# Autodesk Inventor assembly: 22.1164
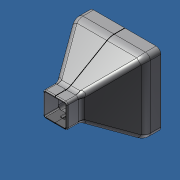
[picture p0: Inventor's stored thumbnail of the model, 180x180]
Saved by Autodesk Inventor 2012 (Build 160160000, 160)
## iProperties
Created: 2018-02
Part Number: 22.1164
Document SubType Name: Assembly
Designer: Admin
Description: COVER FOR FOOT 45
Author: Admin
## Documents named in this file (2)
- Y:\INVENTOR LIBRARIES\PARTS LIBRARY\FEET WHEELS FLOOR FASTENING SUPPORTS\22.1164 COVER FOR FOOT 45.iam
- Y:\INVENTOR LIBRARIES\PARTS LIBRARY\FEET WHEELS FLOOR FASTENING SUPPORTS\SUBCOMPONENTS\22.1164 COVER FOR FOOT 45 HALF.ipt
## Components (2 placed, 1 different names)
1. 22.1164 COVER FOR FOOT 45 HALF:1 — Mate:1, Mate:2, Flush:1, Mate:3, Flush:2, Flush:3
2. 22.1164 COVER FOR FOOT 45 HALF:2 — Mate:3, Flush:2, Flush:3
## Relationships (6: Mate 3, Flush 3)
- Mate:1: 22.1164 COVER FOR FOOT 45 HALF:1
- Mate:2: 22.1164 COVER FOR FOOT 45 HALF:1
- Flush:1: 22.1164 COVER FOR FOOT 45 HALF:1
- Mate:3: 22.1164 COVER FOR FOOT 45 HALF:1 ↔ 22.1164 COVER FOR FOOT 45 HALF:2
- Flush:2: 22.1164 COVER FOR FOOT 45 HALF:1 ↔ 22.1164 COVER FOR FOOT 45 HALF:2
- Flush:3: 22.1164 COVER FOR FOOT 45 HALF:1 ↔ 22.1164 COVER FOR FOOT 45 HALF:2
